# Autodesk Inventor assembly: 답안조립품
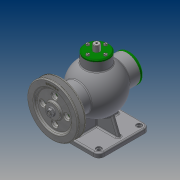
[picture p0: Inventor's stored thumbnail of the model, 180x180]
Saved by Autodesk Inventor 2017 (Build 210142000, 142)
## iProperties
Part Number: 답안조립품
Material: 일반
Document SubType Name: Assembly
Designer: 13
Author: 13
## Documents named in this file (19)
- C:\Users\13\Desktop\480414V1004\답안조립품.iam
- C:\Users\13\Desktop\480414V1004\본체.ipt
- C:\Users\13\Desktop\480414V1004\뒤커버.ipt
- C:\Users\13\Desktop\480414V1004\앞커버.ipt
- C:\Users\13\Desktop\480414V1004\상부커버.ipt
- C:\Users\13\Desktop\480414V1004\슬라이드.ipt
- C:\Users\13\Desktop\480414V1004\편심축.ipt
- C:\Users\13\Desktop\480414V1004\베어링 6202.ipt
- 베어링 6202.ipt
- C:\Users\13\Desktop\480414V1004\부시.ipt
- C:\Users\13\Desktop\480414V1004\멈춤링 15x1.ipt
- C:\Users\13\Desktop\480414V1004\멈춤링 35x1.6.ipt
- 멈춤링 35x1.6.ipt
- C:\Users\13\Desktop\480414V1004\오일 실 15 30 7.ipt
- C:\Users\13\Desktop\480414V1004\V-벨트풀리.ipt
- C:\Users\13\Desktop\480414V1004\키 4x4x12.ipt
- C:\Users\13\Desktop\480414V1004\너트 M8.ipt
- C:\Users\13\Desktop\480414V1004\볼트 M4x16.ipt
- C:\Users\13\Desktop\480414V1004\볼트 M4x12.ipt
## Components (1 placed, 1 different names)
1. V-벨트풀리:1 — 플러쉬:1, 플러쉬:2
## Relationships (2: Flush 2)
- 플러쉬:1 [Flush]: V-벨트풀리:1
- 플러쉬:2 [Flush]: V-벨트풀리:1
